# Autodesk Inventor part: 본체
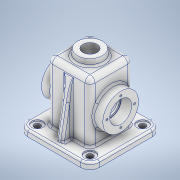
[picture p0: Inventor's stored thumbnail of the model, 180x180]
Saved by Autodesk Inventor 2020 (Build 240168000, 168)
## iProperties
Created: 2021-07
Part Number: 본체
Material: 알루미늄 6061
Document SubType Name: Modeling
Designer: Owner
Density: 2.7 g/cm^3
Appearance: 알루미늄 - 평지
Mass: 771.504 g
Surface Area: 846.734 cm^2
Volume: 285.742 cm^3
Author: Owner
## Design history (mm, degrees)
sketch "스케치1"
  geometry: L1 (-34, 34)-(34, 34); L2 (34, 34)-(34, -34); L3 (34, -34)-(-34, -34); L4 (-34, -34)-(-34, 34); L5 (-34, 34)-(34, -34); L6 (34, 34)-(-34, -34); 1 further point
  constraints: 12 end point, 2 midpoint, 2 parallel, 1 horizontal, 1 perpendicular
  dimensions: "d0" = 68 distance of L2.end L3.end; "d1" = 68 distance of L1.end L2.end
extrude "돌출1" new body sketch "스케치1" distance "d2" = 105; taper "d3" = 0 deg
sketch "스케치2"
  geometry: L1 (-29, 29)-(29, 29); L2 (29, 29)-(29, -29); L3 (29, -29)-(-29, -29); L4 (-29, -29)-(-29, 29); L5 (-29, 29)-(29, -29); L6 (29, 29)-(-29, -29); 1 further point
  constraints: 12 end point, 2 midpoint, 2 parallel, 1 horizontal, 1 perpendicular
  dimensions: "d4" = 58 distance of L2.end L3.end; "d5" = 58 distance of L1.end L2.end
extrude "돌출2" cut sketch "스케치2" distance "d6" = 100; taper "d7" = 0 deg
fillet "모깎기1" dims "d8" = 8
sketch "스케치3"
  geometry: L1 (-57, 57)-(57, 57); L2 (57, 57)-(57, -57); L3 (57, -57)-(-57, -57); L4 (-57, -57)-(-57, 57); L5 (-57, 57)-(57, -57); L6 (57, 57)-(-57, -57); L7 (34, 26)-(34, -26) reference; L8 (-26, 34)-(26, 34) reference; L9 (-34, -26)-(-34, 26) reference; L10 (26, -34)-(-26, -34) reference; L11 (21, -29)-(-21, -29) reference; L12 (-29, -21)-(-29, 21) reference; L13 (-21, 29)-(21, 29) reference; L14 (29, 21)-(29, -21) reference; A1 r 8 centre (26, -26) between (26, -34) and (34, -26) reference; A2 r 8 centre (26, 26) between (34, 26) and (26, 34) reference; A3 r 8 centre (-26, 26) between (-26, 34) and (-34, 26) reference; A4 r 8 centre (-26, -26) between (-34, -26) and (-26, -34) reference; A5 r 8 centre (-21, -21) between (-29, -21) and (-21, -29) reference; A6 r 8 centre (-21, 21) between (-21, 29) and (-29, 21) reference; A7 r 8 centre (21, 21) between (29, 21) and (21, 29) reference; A8 r 8 centre (21, -21) between (21, -29) and (29, -21) reference; 1 further point
  constraints: 12 end point, 2 midpoint, 2 parallel, 1 horizontal, 1 perpendicular
  dimensions: "d9" = 114 distance of L2.end L3.end; "d10" = 114 distance of L1.end L2.end
extrude "돌출3" join sketch "스케치3" distance "d11" = 10; taper "d12" = 0 deg
fillet "모깎기2" dims "d13" = 15
node "작업 평면1"
sketch "스케치4"
  geometry: C1 r 20 at (0, 0); 1 further point
  constraints: 1 centre point, 1 coincident
  dimensions: "d16" = 40 diameter of C1
extrude "돌출4" join sketch "스케치4" stored distance "d17" = 10; taper "d18" = 8 deg
node "작업 평면2"
sketch "스케치5"
  geometry: L1 (26, -97)-(26, -45); C1 r 28.5 at (26, -45)
  constraints: 2 end point, 1 centre point, 1 coincident, 1 vertical
  dimensions: "d20" = 52 distance of L1.start L1.end; "d21" = 57 diameter of C1
extrude "돌출5" join sketch "스케치5" distance "d22" = 17.25; taper "d23" = 0 deg
node "작업 평면3"
sketch "스케치6"
  geometry: L1 (26, -97)-(26, -45); C1 r 28.5 at (26, -45)
  constraints: 2 end point, 1 centre point, 1 coincident, 1 vertical
  dimensions: "d25" = 52 distance of L1.start L1.end; "d26" = 57 diameter of C1
extrude "돌출6" join sketch "스케치6" distance "d27" = 19.25; taper "d28" = 0 deg
sketch "스케치7" dims "d29" = 44
  geometry: C1 r 2.371 at (0, 22); C2 r 2.371 at (-22, 0); C3 r 2.371 at (0, -22); C4 r 2.371 at (22, 0); 2 further points
  constraints: 4 centre point, 1 vertical alignment, 11 other
  dimensions: "d32" = 360 deg dimension on point (0, 0) C1.centre (derived)
hole "구멍1" sketch "스케치7" at (-22, 0), (0, -22), (22, 0), (0, 22) diameter "d34" = 3.242; stored, may be unused: countersink angle "d38" = 90 deg, drill point angle "d40" = 118 deg; dims "d35" = 8, "d36" = 4, "d37" = 2, "d39" = 10
sketch "스케치8"
  geometry: C1 r 1.621 at (0, -22) reference; C2 r 1.621 at (0, -22); C3 r 1.621 at (22, 0) reference; C4 r 1.621 at (22, 0); C5 r 1.622 at (0, 22); C6 r 1.779 at (-22, 0); A1 r 22 centre (0, 0) between (0, 22) and (-22, 0); 1 further point
  constraints: 5 centre point, 2 coincident, 2 point on circle
  dimensions: "d41" = 44 diameter of A1
hole "구멍2" sketch "스케치8" at (0, 22), (22, 0), (0, -22), (-22, 0) diameter "d42" = 3.242; stored, may be unused: countersink angle "d46" = 90 deg, drill point angle "d48" = 118 deg; dims "d43" = 8, "d44" = 4, "d45" = 2, "d47" = 10
sketch "스케치9"
  geometry: C1 r 17.5 at (0, 0); 1 further point
  constraints: 1 centre point
  dimensions: "d49" = 35 diameter of C1
extrude "돌출7" cut sketch "스케치9" distance "d50" = 17; taper "d51" = 0 deg
sketch "스케치10"
  geometry: C1 r 17.5 at (0, 0); 1 further point
  constraints: 1 centre point
extrude "돌출8" cut sketch "스케치10" distance "d52" = 17; taper "d53" = 0 deg
sketch "스케치11"
  geometry: C1 r 15 at (0, 0); 1 further point
  constraints: 1 centre point
  dimensions: "d54" = 30 diameter of C1
extrude "돌출9" cut sketch "스케치11" distance "d55" = 3; taper "d56" = 0 deg
sketch "스케치12"
  geometry: C1 r 15 at (0, 0); 1 further point
  constraints: 1 centre point
  dimensions: "d57" = 30 diameter of C1
extrude "돌출10" cut sketch "스케치12" distance "d58" = 3; taper "d59" = 0 deg
fillet "모깎기4" dims "d60" = 0.3
sketch "스케치13"
  geometry: C1 r 12.5 at (0, 0); 1 further point
  constraints: 1 centre point, 1 coincident
  dimensions: "d61" = 25 diameter of C1
hole "구멍3" sketch "스케치13" at (0, 0) diameter "d62" = 22.83494; stored, may be unused: countersink angle "d66" = 90 deg, drill point angle "d68" = 0 deg; dims "d63" = 50, "d64" = 4, "d65" = 2, "d67" = 59.3
node "작업 평면4"
fillet "모깎기5" dims "d75" = 3
sketch "스케치15"
  geometry: L1 (-36, 0)-(-36, 7) reference; L2 (-33, 10)-(-21, 10) reference; L3 (-28, 10)-(-18.531, 63.701); 1 further point
  constraints: 2 end point, 1 point on line
  dimensions: "d77" = 10 deg angle of L1 L3; "d78" = 8 distance from line of L1 L3.start
feature "리브1" sketch "스케치15" dims "d79" = 1, "d80" = 10, "d81" = 0, "d82" = 0, "d83" = 1, "d84" = 1
node "작업 평면5"
fillet "모깎기6" dims "d85" = 3
fillet "모깎기7" dims "d86" = 3
sketch "스케치16"
  geometry: C1 r 9 at (42, -42); C2 r 9 at (42, 42); C3 r 9 at (-42, 42); C4 r 9 at (-42, -42); A1 r 12 centre (42, -42) between (42, -54) and (54, -42) reference; A2 r 12 centre (42, 42) between (54, 42) and (42, 54) reference; A3 r 12 centre (-42, 42) between (-42, 54) and (-54, 42) reference; A4 r 12 centre (-42, -42) between (-54, -42) and (-42, -54) reference; 1 further point
  constraints: 4 centre point, 4 coincident
  dimensions: "d87" = 18 diameter of C1; "d88" = 18 diameter of C2; "d89" = 18 diameter of C3; "d90" = 18 diameter of C4
extrude "돌출11" cut sketch "스케치16" distance "d91" = 2; taper "d92" = 0 deg
sketch "스케치17"
  geometry: C1 r 9 at (0, 0) reference; C2 r 5 at (0, 0); C3 r 9 at (-84, 0) reference; C4 r 5 at (-84, 0); C5 r 9 at (-84, -84) reference; C6 r 5 at (-84, -84); C7 r 9 at (0, -84) reference; C8 r 5 at (0, -84); 1 further point
  constraints: 4 centre point, 4 coincident
  dimensions: "d93" = 10 diameter of C2; "d94" = 10 diameter of C4; "d95" = 10 diameter of C6; "d96" = 10 diameter of C8
extrude "돌출12" cut sketch "스케치17" stored distance "d97" = 2; taper "d98" = 0 deg
fillet "모깎기8" dims "d99" = 3
sketch "스케치18"
  geometry: L1 (46, 18)-(6, 18) reference; L2 (37.417, 3)-(14.583, 3) reference; 3 further points
  constraints: 1 midpoint, 1 vertical alignment, 1 other
  dimensions: "d102" = 25 distance from line of point (26, -7) L1
extrude "돌출13" join sketch "스케치18" distance "d103" = 0.5; taper "d104" = 0 deg
node "솔리드1"
mirror "미러1"
node "투영된 루프1"
feature "A9D066F2-1C7D-4E18-AEED-F7BC21143FA4" dims "d34" = 3.242, "d35" = 8, "d36" = 4, "d37" = 2, "d38" = 90 deg, "d39" = 10, "d40" = 118 deg
other parameters: "d15" = 105, "d19" = 15, "d24" = 15
